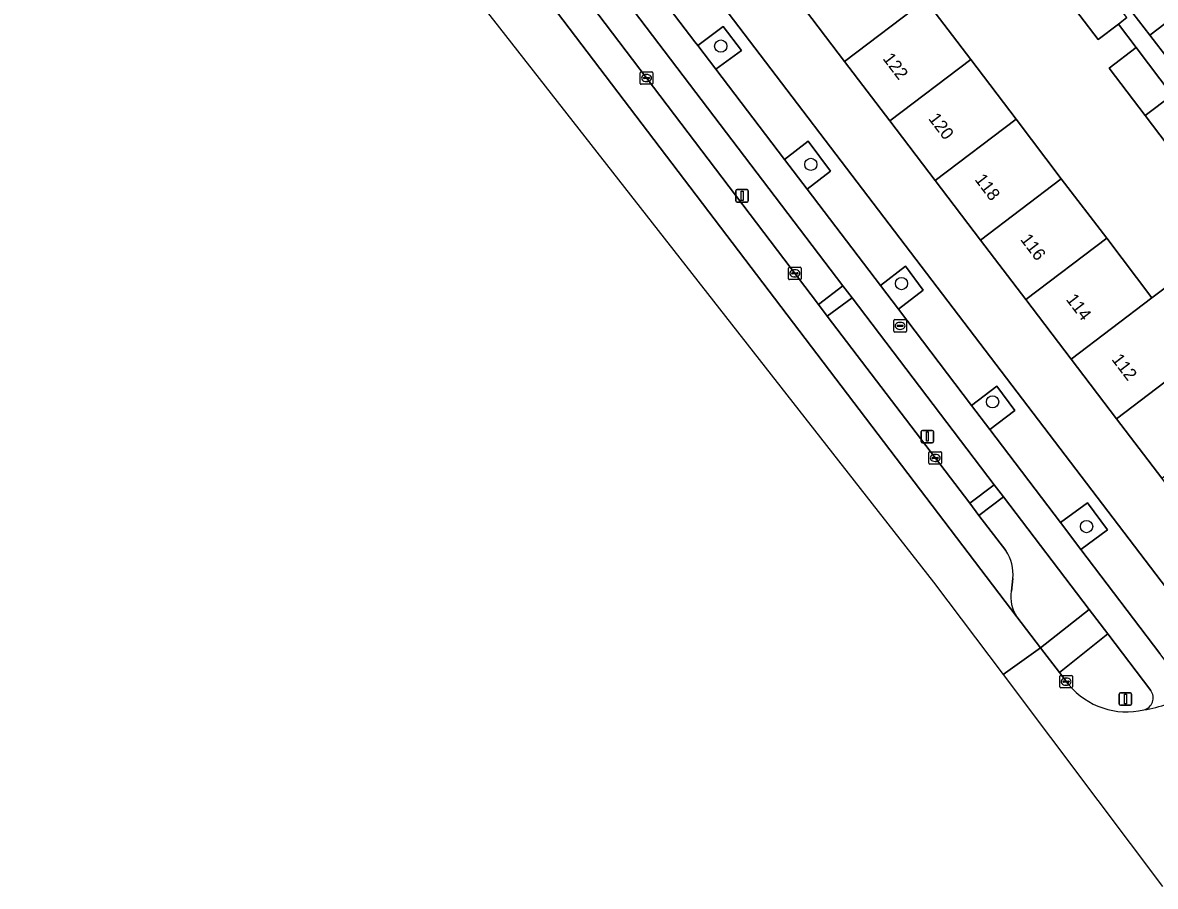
# Model space of a CAD drawing. Extents: x 160030 to 160839, y 385325 to 386450.
# Drawn here: x 160199.8 to 160290.3, y 385749.7 to 385818.7 of the extents above; entities that cross this region are included whole.
import ezdxf

# ---------------------------------------------------------------- set-up
doc = ezdxf.new("R2010")
doc.units = 0
for name, color, linetype in [('IMGEO_Berm_groen', 7, 'Continuous'), ('IMGEO_Boom', 7, 'Continuous'), ('IMGEO_Erf', 7, 'Continuous'), ('IMGEO_Fietspad_gesloten', 7, 'Continuous'), ('IMGEO_Groenvoorziening', 7, 'Continuous'), ('IMGEO_Kolk', 7, 'Continuous'), ('IMGEO_Lichtmast', 7, 'Continuous'), ('IMGEO_Pand', 7, 'Continuous'), ('IMGEO_Pand_nummerreeks', 7, 'Continuous'), ('IMGEO_Parkeervlak_open', 7, 'Continuous'), ('IMGEO_Rijbaan_lokaal_gesloten', 7, 'Continuous'), ('IMGEO_Rioolput', 7, 'Continuous'), ('IMGEO_Verkeerseiland_groen', 7, 'Continuous'), ('IMGEO_Voetpad_open', 7, 'Continuous')]:
    doc.layers.add(name, color=color, linetype=linetype)

msp = doc.modelspace()

# ---------------------------------------------------------------- linework, layer by layer
at = {"layer": 'IMGEO_Berm_groen'}
for points in [[(160247.179, 385821.566), (160245.256, 385820.064), (160263.382, 385796.182), (160265.333, 385797.683)], [(160266.08, 385796.701), (160264.086, 385795.256), (160275.455, 385780.303), (160277.414, 385781.789)]]:
    msp.add_lwpolyline(points, close=True, dxfattribs=at)
for points in [[(160278.156, 385780.813), (160276.196, 385779.33), (160278.331, 385776.525)], [(160279.223, 385771.231), (160281.119, 385768.748), (160284.988, 385771.823), (160278.156, 385780.813)], [(160278.902, 385774.282), (160278.781, 385773.271)]]:
    msp.add_lwpolyline(points, dxfattribs=at)
for centre, radius, start, end in [((160275.582, 385774.631), 3.338, 353.99921, 34.5656), ((160281.543, 385772.802), 2.802, 170.35531, 214.09493)]:
    msp.add_arc(centre, radius, start, end, dxfattribs=at)
at = {"layer": 'IMGEO_Boom'}
for centre in [(160255.58, 385816.818), (160262.773, 385807.373), (160270.013, 385797.851), (160277.282, 385788.403), (160284.788, 385778.442)]:
    msp.add_circle(centre, 0.489, dxfattribs=at)
at = {"layer": 'IMGEO_Erf'}
for points in [[(160231.475, 385851.922), (160294.583, 385769.052)], [(160292.389, 385807.402), (160289.46, 385811.27), (160286.594, 385815.056), (160288.76, 385816.696), (160287.329, 385818.58), (160285.703, 385817.345), (160282.773, 385821.214)], [(160304.666, 385777.443), (160298.219, 385772.539), (160294.413, 385777.543), (160290.795, 385782.299), (160287.176, 385787.057), (160283.557, 385791.815), (160279.938, 385796.572), (160276.32, 385801.329), (160272.701, 385806.086), (160269.083, 385810.842), (160265.465, 385815.599), (160261.846, 385820.356)], [(160271.917, 385820.496), (160275.536, 385815.739), (160279.154, 385810.982), (160282.772, 385806.225), (160286.392, 385801.467), (160290.009, 385796.711), (160292.436, 385798.553)], [(160288.481, 385819.459), (160289.842, 385817.685), (160292.178, 385819.479)]]:
    msp.add_lwpolyline(points, dxfattribs=at)
at = {"layer": 'IMGEO_Fietspad_gesloten'}
for points in [[(160255.179, 385814.968), (160253.742, 385816.855), (160253.509, 385817.161), (160247.864, 385824.573), (160246.034, 385826.977), (160241.998, 385832.275), (160240.606, 385834.102), (160240.383, 385834.395), (160233.264, 385843.741), (160231.245, 385846.393), (160228.63, 385849.846), (160226.256, 385852.983)], [(160225.501, 385850.09), (160229.487, 385844.842), (160230.756, 385843.173), (160246.466, 385822.505), (160247.179, 385821.566), (160265.333, 385797.683), (160266.08, 385796.701), (160277.414, 385781.789), (160278.156, 385780.813), (160284.988, 385771.823), (160286.475, 385769.866), (160289.911, 385765.345)], [(160293.027, 385765.153), (160290.63, 385768.308), (160284.323, 385776.61), (160282.698, 385778.755), (160277.06, 385786.195), (160275.612, 385788.106), (160269.782, 385795.793), (160268.333, 385797.697), (160262.479, 385805.383), (160260.678, 385807.747), (160255.179, 385814.968)]]:
    msp.add_lwpolyline(points, dxfattribs=at)
for centre, radius, start, end in [((160289.114, 385764.759), 0.989, 284.16509, 36.31597), ((160287.825, 385773.612), 9.93, 278.87106, 301.59313)]:
    msp.add_arc(centre, radius, start, end, dxfattribs=at)
at = {"layer": 'IMGEO_Groenvoorziening'}
for points in [[(160255.765, 385818.395), (160253.742, 385816.855), (160255.179, 385814.968), (160257.239, 385816.477)], [(160262.55, 385809.216), (160260.678, 385807.747), (160262.479, 385805.383), (160264.347, 385806.834)], [(160270.343, 385799.251), (160268.333, 385797.697), (160269.782, 385795.793), (160271.74, 385797.335)], [(160277.631, 385789.658), (160275.612, 385788.106), (160277.06, 385786.195), (160279.057, 385787.714)], [(160284.866, 385780.351), (160282.698, 385778.755), (160284.323, 385776.61), (160286.469, 385778.175)]]:
    msp.add_lwpolyline(points, close=True, dxfattribs=at)
at = {"layer": 'IMGEO_Kolk'}
for p, q in [((160249.156, 385813.84), (160249.156, 385814.692)), ((160249.231, 385814.766), (160250.083, 385814.766)), ((160249.415, 385814.26), (160249.415, 385814.272)), ((160249.853, 385814.223), (160249.455, 385814.223)), ((160249.458, 385814.309), (160249.856, 385814.309)), ((160249.667, 385813.986), (160249.642, 385813.986)), ((160249.644, 385814.546), (160249.669, 385814.546)), ((160249.899, 385814.272), (160249.899, 385814.26)), ((160250.157, 385814.692), (160250.157, 385813.84)), ((160250.083, 385813.766), (160249.231, 385813.766)), ((160260.995, 385798.241), (160260.995, 385799.093)), ((160261.07, 385799.167), (160261.922, 385799.167)), ((160261.254, 385798.661), (160261.254, 385798.673)), ((160261.692, 385798.624), (160261.294, 385798.624)), ((160261.297, 385798.71), (160261.695, 385798.71)), ((160261.483, 385798.947), (160261.508, 385798.947)), ((160261.738, 385798.673), (160261.738, 385798.661)), ((160261.996, 385799.093), (160261.996, 385798.241)), ((160261.922, 385798.167), (160261.07, 385798.167)), ((160261.506, 385798.387), (160261.481, 385798.387)), ((160272.202, 385783.497), (160272.202, 385784.349)), ((160272.277, 385784.423), (160273.129, 385784.423)), ((160272.69, 385784.203), (160272.715, 385784.203)), ((160273.203, 385784.349), (160273.203, 385783.497)), ((160273.129, 385783.423), (160272.277, 385783.423)), ((160272.461, 385783.917), (160272.461, 385783.929)), ((160272.899, 385783.88), (160272.501, 385783.88)), ((160272.504, 385783.966), (160272.902, 385783.966)), ((160272.713, 385783.643), (160272.688, 385783.643)), ((160272.945, 385783.929), (160272.945, 385783.917)), ((160282.652, 385765.63), (160282.652, 385766.482)), ((160282.727, 385766.556), (160283.579, 385766.556)), ((160282.911, 385766.05), (160282.911, 385766.062)), ((160283.349, 385766.013), (160282.951, 385766.013)), ((160282.954, 385766.099), (160283.352, 385766.099)), ((160283.14, 385766.336), (160283.165, 385766.336)), ((160283.395, 385766.062), (160283.395, 385766.05)), ((160283.653, 385766.482), (160283.653, 385765.63)), ((160283.579, 385765.556), (160282.727, 385765.556)), ((160283.163, 385765.776), (160283.138, 385765.776))]:
    msp.add_line(p, q, dxfattribs=at)
for points in [[(160249.156, 385813.84), (160249.156, 385814.692)], [(160249.231, 385814.766), (160250.083, 385814.766)], [(160250.157, 385814.692), (160250.157, 385813.84)], [(160250.083, 385813.766), (160249.231, 385813.766)], [(160260.995, 385798.241), (160260.995, 385799.093)], [(160261.07, 385799.167), (160261.922, 385799.167)], [(160261.996, 385799.093), (160261.996, 385798.241)], [(160261.922, 385798.167), (160261.07, 385798.167)], [(160272.202, 385783.497), (160272.202, 385784.349)], [(160272.277, 385784.423), (160273.129, 385784.423)], [(160273.203, 385784.349), (160273.203, 385783.497)], [(160273.129, 385783.423), (160272.277, 385783.423)], [(160282.652, 385765.63), (160282.652, 385766.482)], [(160282.727, 385766.556), (160283.579, 385766.556)], [(160283.653, 385766.482), (160283.653, 385765.63)], [(160283.579, 385765.556), (160282.727, 385765.556)]]:
    msp.add_lwpolyline(points, dxfattribs=at)
for centre, radius, start, end in [((160249.233, 385814.69), 0.0765, 91.55205, 178.44795), ((160249.233, 385814.69), 0.0765, 91.55205, 178.44795), ((160249.455, 385814.269), 0.0403, 85.87752, 175.75265), ((160249.452, 385814.259), 0.0366, 178.93798, 274.71019), ((160249.856, 385814.266), 0.043, 264.86636, 352.45326), ((160249.86, 385814.271), 0.0386, 1.73085, 96.63898), ((160250.081, 385814.69), 0.0765, 1.55205, 88.44795), ((160250.081, 385814.69), 0.0765, 1.55205, 88.44795), ((160249.233, 385813.842), 0.0765, 181.55205, 268.44795), ((160249.233, 385813.842), 0.0765, 181.55205, 268.44795), ((160250.081, 385813.842), 0.0765, 271.55205, 358.44795), ((160250.081, 385813.842), 0.0765, 271.55205, 358.44795), ((160261.072, 385799.091), 0.0765, 91.55205, 178.44795), ((160261.072, 385799.091), 0.0765, 91.55205, 178.44795), ((160261.294, 385798.67), 0.0403, 85.87752, 175.75265), ((160261.291, 385798.66), 0.0366, 178.93798, 274.71019), ((160261.695, 385798.667), 0.043, 264.86636, 352.45326), ((160261.699, 385798.672), 0.0386, 1.73085, 96.63898), ((160261.92, 385799.091), 0.0765, 1.55205, 88.44795), ((160261.92, 385799.091), 0.0765, 1.55205, 88.44795), ((160261.072, 385798.243), 0.0765, 181.55205, 268.44795), ((160261.072, 385798.243), 0.0765, 181.55205, 268.44795), ((160261.92, 385798.243), 0.0765, 271.55205, 358.44795), ((160261.92, 385798.243), 0.0765, 271.55205, 358.44795), ((160272.279, 385784.347), 0.0765, 91.55205, 178.44795), ((160272.279, 385784.347), 0.0765, 91.55205, 178.44795), ((160273.127, 385784.347), 0.0765, 1.55205, 88.44795), ((160273.127, 385784.347), 0.0765, 1.55205, 88.44795), ((160272.279, 385783.499), 0.0765, 181.55205, 268.44795), ((160272.279, 385783.499), 0.0765, 181.55205, 268.44795), ((160272.501, 385783.926), 0.0403, 85.87752, 175.75265), ((160272.498, 385783.916), 0.0366, 178.93798, 274.71019), ((160272.902, 385783.923), 0.043, 264.86636, 352.45326), ((160272.906, 385783.928), 0.0386, 1.73085, 96.63898), ((160273.127, 385783.499), 0.0765, 271.55205, 358.44795), ((160273.127, 385783.499), 0.0765, 271.55205, 358.44795), ((160282.729, 385766.48), 0.0765, 91.55205, 178.44795), ((160282.729, 385766.48), 0.0765, 91.55205, 178.44795), ((160282.951, 385766.059), 0.0403, 85.87752, 175.75265), ((160282.948, 385766.049), 0.0366, 178.93798, 274.71019), ((160283.352, 385766.056), 0.043, 264.86636, 352.45326), ((160283.356, 385766.061), 0.0386, 1.73085, 96.63898), ((160283.577, 385766.48), 0.0765, 1.55205, 88.44795), ((160283.577, 385766.48), 0.0765, 1.55205, 88.44795), ((160282.729, 385765.632), 0.0765, 181.55205, 268.44795), ((160282.729, 385765.632), 0.0765, 181.55205, 268.44795), ((160283.577, 385765.632), 0.0765, 271.55205, 358.44795), ((160283.577, 385765.632), 0.0765, 271.55205, 358.44795)]:
    msp.add_arc(centre, radius, start, end, dxfattribs=at)
for centre, major_axis, ratio, start_param, end_param in [((160249.643, 385814.266), (-0.387, 0.002), 0.722429, 4.712389, 7.853982), ((160249.668, 385814.266), (-0.39, 0.002), 0.717154, 1.570796, 4.712389), ((160261.482, 385798.667), (-0.387, 0.002), 0.722429, 4.712389, 7.853982), ((160261.507, 385798.667), (-0.39, 0.002), 0.717154, 1.570796, 4.712389), ((160272.689, 385783.923), (-0.387, 0.002), 0.722429, 4.712389, 7.853982), ((160272.714, 385783.923), (-0.39, 0.002), 0.717154, 1.570796, 4.712389), ((160283.139, 385766.056), (-0.387, 0.002), 0.722429, 4.712389, 7.853982), ((160283.164, 385766.056), (-0.39, 0.002), 0.717154, 1.570796, 4.712389)]:
    msp.add_ellipse(centre, major_axis=major_axis, ratio=ratio, start_param=start_param, end_param=end_param, dxfattribs=at)
at = {"layer": 'IMGEO_Lichtmast'}
for p, q in [((160256.791, 385804.457), (160256.791, 385805.257)), ((160256.791, 385805.257), (160256.791, 385804.457)), ((160256.891, 385805.357), (160257.681, 385805.357)), ((160257.681, 385805.357), (160256.891, 385805.357)), ((160257.781, 385805.257), (160257.781, 385804.457)), ((160257.781, 385804.457), (160257.781, 385805.257)), ((160257.681, 385804.357), (160256.891, 385804.357)), ((160256.891, 385804.357), (160257.681, 385804.357)), ((160271.581, 385785.227), (160271.581, 385786.027)), ((160271.581, 385786.027), (160271.581, 385785.227)), ((160271.681, 385786.127), (160272.471, 385786.127)), ((160272.471, 385786.127), (160271.681, 385786.127)), ((160272.571, 385786.027), (160272.571, 385785.227)), ((160272.571, 385785.227), (160272.571, 385786.027)), ((160272.471, 385785.127), (160271.681, 385785.127)), ((160271.681, 385785.127), (160272.471, 385785.127)), ((160287.394, 385764.27), (160287.394, 385765.07)), ((160287.394, 385765.07), (160287.394, 385764.27)), ((160287.494, 385765.17), (160288.284, 385765.17)), ((160288.284, 385765.17), (160287.494, 385765.17)), ((160288.384, 385765.07), (160288.384, 385764.27)), ((160288.384, 385764.27), (160288.384, 385765.07)), ((160288.284, 385764.17), (160287.494, 385764.17)), ((160287.494, 385764.17), (160288.284, 385764.17))]:
    msp.add_line(p, q, dxfattribs=at)
for points in [[(160257.211, 385805.232), (160257.361, 385805.232), (160257.361, 385804.482), (160257.211, 385804.482), (160257.211, 385805.232)], [(160272.001, 385786.002), (160272.151, 385786.002), (160272.151, 385785.252), (160272.001, 385785.252), (160272.001, 385786.002)], [(160287.814, 385765.045), (160287.964, 385765.045), (160287.964, 385764.295), (160287.814, 385764.295), (160287.814, 385765.045)]]:
    msp.add_lwpolyline(points, dxfattribs=at)
for centre, start, end in [((160256.891, 385805.257), 90, 180), ((160256.891, 385805.257), 90, 180), ((160257.681, 385805.257), 0, 90), ((160257.681, 385805.257), 360, 90), ((160256.891, 385804.457), 180, 270), ((160256.891, 385804.457), 180, 270), ((160257.681, 385804.457), 270, 0), ((160257.681, 385804.457), 270, 0), ((160271.681, 385786.027), 90, 180), ((160271.681, 385786.027), 90, 180), ((160272.471, 385786.027), 0, 90), ((160272.471, 385786.027), 360, 90), ((160271.681, 385785.227), 180, 270), ((160271.681, 385785.227), 180, 270), ((160272.471, 385785.227), 270, 0), ((160272.471, 385785.227), 270, 0), ((160287.494, 385765.07), 90, 180), ((160287.494, 385765.07), 90, 180), ((160288.284, 385765.07), 0, 90), ((160288.284, 385765.07), 360, 90), ((160287.494, 385764.27), 180, 270), ((160287.494, 385764.27), 180, 270), ((160288.284, 385764.27), 270, 0), ((160288.284, 385764.27), 270, 0)]:
    msp.add_arc(centre, 0.1, start, end, dxfattribs=at)
at = {"layer": 'IMGEO_Pand'}
for points in [[(160271.917, 385820.496), (160274.802, 385822.686), (160271.19, 385827.447), (160268.299, 385825.253), (160261.846, 385820.356), (160265.465, 385815.599)], [(160285.083, 385822.963), (160282.773, 385821.214), (160285.703, 385817.345), (160287.329, 385818.58), (160288.011, 385819.098)], [(160275.536, 385815.739), (160271.917, 385820.496), (160265.465, 385815.599), (160269.083, 385810.842)], [(160295.203, 385815.538), (160292.178, 385819.479), (160289.842, 385817.685), (160292.859, 385813.755)], [(160288.76, 385816.696), (160286.594, 385815.056), (160289.46, 385811.27), (160291.626, 385812.91)], [(160269.083, 385810.842), (160272.701, 385806.086), (160279.154, 385810.982), (160275.536, 385815.739)], [(160291.626, 385812.91), (160289.46, 385811.27), (160292.389, 385807.402), (160294.555, 385809.042)], [(160282.772, 385806.225), (160279.154, 385810.982), (160272.701, 385806.086), (160276.32, 385801.329)], [(160276.32, 385801.329), (160279.938, 385796.572), (160286.392, 385801.467), (160282.772, 385806.225)], [(160290.009, 385796.711), (160286.392, 385801.467), (160279.938, 385796.572), (160283.557, 385791.815)], [(160293.628, 385791.954), (160296.049, 385793.792), (160292.436, 385798.553), (160290.009, 385796.711), (160283.557, 385791.815), (160287.176, 385787.057)], [(160287.176, 385787.057), (160290.795, 385782.299), (160297.247, 385787.197), (160293.628, 385791.954)]]:
    msp.add_lwpolyline(points, close=True, dxfattribs=at)
at = {"layer": 'IMGEO_Parkeervlak_open'}
for points in [[(160228.526, 385837.944), (160279.223, 385771.231)], [(160278.331, 385776.525), (160276.196, 385779.33), (160275.455, 385780.303), (160264.086, 385795.256), (160263.382, 385796.182), (160245.256, 385820.064), (160244.52, 385821.036), (160233.389, 385835.707)], [(160278.781, 385773.271), (160278.902, 385774.282)]]:
    msp.add_lwpolyline(points, dxfattribs=at)
for centre, radius, start, end in [((160275.582, 385774.631), 3.338, 353.99921, 34.5656), ((160281.543, 385772.802), 2.802, 170.35531, 214.09493)]:
    msp.add_arc(centre, radius, start, end, dxfattribs=at)
at = {"layer": 'IMGEO_Rijbaan_lokaal_gesloten'}
msp.add_lwpolyline([(160278.119, 385766.625), (160281.119, 385768.748), (160279.223, 385771.231), (160228.526, 385837.944), (160226.826, 385840.11), (160225.579, 385841.807), (160224.418, 385843.405), (160212.483, 385859.092), (160208.116, 385864.799), (160181.103, 385900.416), (160180.357, 385901.406), (160179.584, 385902.465), (160175.453, 385899.617), (160202.503, 385863.561), (160272.577, 385773.993)], close=True, dxfattribs=at)
for points in [[(160283.372, 385765.797), (160282.625, 385766.776), (160281.119, 385768.748), (160278.119, 385766.625)], [(160278.119, 385766.625), (160285.69, 385756.559), (160290.844, 385749.707)]]:
    msp.add_lwpolyline(points, dxfattribs=at)
for centre, radius, start, end in [((160287.99, 385769.67), 6.027, 219.98749, 283.1024), ((160287.825, 385773.612), 9.93, 278.87106, 301.59313)]:
    msp.add_arc(centre, radius, start, end, dxfattribs=at)
at = {"layer": 'IMGEO_Rioolput'}
for p, q in [((160269.473, 385794.973), (160270.325, 385794.973)), ((160269.398, 385794.047), (160269.398, 385794.899)), ((160269.657, 385794.467), (160269.657, 385794.479)), ((160270.095, 385794.43), (160269.697, 385794.43)), ((160269.7, 385794.516), (160270.098, 385794.516)), ((160269.909, 385794.193), (160269.884, 385794.193)), ((160269.886, 385794.753), (160269.911, 385794.753)), ((160270.141, 385794.479), (160270.141, 385794.467)), ((160270.399, 385794.899), (160270.399, 385794.047)), ((160270.325, 385793.973), (160269.473, 385793.973))]:
    msp.add_line(p, q, dxfattribs=at)
for points in [[(160269.473, 385794.973), (160270.325, 385794.973)], [(160269.398, 385794.047), (160269.398, 385794.899)], [(160270.399, 385794.899), (160270.399, 385794.047)], [(160270.325, 385793.973), (160269.473, 385793.973)]]:
    msp.add_lwpolyline(points, dxfattribs=at)
for centre, radius, start, end in [((160269.475, 385794.897), 0.0765, 91.55205, 178.44795), ((160269.475, 385794.897), 0.0765, 91.55205, 178.44795), ((160270.323, 385794.897), 0.0765, 1.55205, 88.44795), ((160270.323, 385794.897), 0.0765, 1.55205, 88.44795), ((160269.475, 385794.049), 0.0765, 181.55205, 268.44795), ((160269.475, 385794.049), 0.0765, 181.55205, 268.44795), ((160269.697, 385794.476), 0.0403, 85.87752, 175.75265), ((160269.694, 385794.466), 0.0366, 178.93798, 274.71019), ((160270.098, 385794.473), 0.043, 264.86636, 352.45326), ((160270.102, 385794.478), 0.0386, 1.73085, 96.63898), ((160270.323, 385794.049), 0.0765, 271.55205, 358.44795), ((160270.323, 385794.049), 0.0765, 271.55205, 358.44795)]:
    msp.add_arc(centre, radius, start, end, dxfattribs=at)
for centre, major_axis, ratio, start_param, end_param in [((160269.885, 385794.473), (-0.387, 0.002), 0.722429, 4.712389, 7.853982), ((160269.91, 385794.473), (-0.39, 0.002), 0.717154, 1.570796, 4.712389)]:
    msp.add_ellipse(centre, major_axis=major_axis, ratio=ratio, start_param=start_param, end_param=end_param, dxfattribs=at)
at = {"layer": 'IMGEO_Verkeerseiland_groen'}
for points in [[(160286.475, 385769.866), (160282.625, 385766.776), (160283.372, 385765.797)], [(160289.911, 385765.345), (160286.475, 385769.866)]]:
    msp.add_lwpolyline(points, dxfattribs=at)
for centre, radius, start, end in [((160287.99, 385769.67), 6.027, 219.98749, 283.1024), ((160289.114, 385764.759), 0.989, 284.16509, 36.31597)]:
    msp.add_arc(centre, radius, start, end, dxfattribs=at)
at = {"layer": 'IMGEO_Voetpad_open'}
for points in [[(160296.233, 385766.885), (160294.598, 385769.03), (160294.583, 385769.052), (160231.475, 385851.922)], [(160247.864, 385824.573), (160253.509, 385817.161), (160253.742, 385816.855), (160255.765, 385818.395), (160257.239, 385816.477), (160255.179, 385814.968), (160260.678, 385807.747), (160262.55, 385809.216), (160264.347, 385806.834), (160262.479, 385805.383), (160268.333, 385797.697), (160270.343, 385799.251), (160271.74, 385797.335), (160269.782, 385795.793), (160275.612, 385788.106), (160277.631, 385789.658), (160279.057, 385787.714), (160277.06, 385786.195), (160282.698, 385778.755), (160284.866, 385780.351)], [(160292.859, 385813.755), (160289.842, 385817.685), (160288.481, 385819.459)], [(160288.011, 385819.098), (160287.329, 385818.58), (160288.76, 385816.696), (160291.626, 385812.91)], [(160284.866, 385780.351), (160286.469, 385778.175), (160284.323, 385776.61), (160290.63, 385768.308)]]:
    msp.add_lwpolyline(points, dxfattribs=at)
for points in [[(160265.333, 385797.683), (160263.382, 385796.182), (160264.086, 385795.256), (160266.08, 385796.701)], [(160278.156, 385780.813), (160277.414, 385781.789), (160275.455, 385780.303), (160276.196, 385779.33)], [(160286.475, 385769.866), (160284.988, 385771.823), (160281.119, 385768.748), (160282.625, 385766.776)]]:
    msp.add_lwpolyline(points, close=True, dxfattribs=at)

# ---------------------------------------------------------------- texts
at = {"layer": 'IMGEO_Pand_nummerreeks'}
for s, rotation, p in [('122', 307.25911, (160268.469, 385815.812)), ('120', 307.25911, (160272.117, 385811.016)), ('118', 307.25911, (160275.815, 385806.153)), ('116', 307.25911, (160279.458, 385801.365)), ('114', 307.25911, (160283.103, 385796.574)), ('112', 307.25923, (160286.745, 385791.786))]:
    msp.add_text(s, height=1, rotation=rotation, dxfattribs=at).set_placement(p)

doc.saveas('drawing.dxf')
